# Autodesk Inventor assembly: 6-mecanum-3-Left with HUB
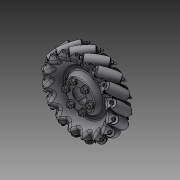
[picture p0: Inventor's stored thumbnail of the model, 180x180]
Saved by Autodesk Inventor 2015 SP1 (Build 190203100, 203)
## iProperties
Created: 2015-01
Part Number: 6-mecanum-3-Left with HUB
Document SubType Name: Assembly
Designer: TODD D MILLER
Mass: 713.537 g
Surface Area: 1552.75 cm^2
Volume: 208.67 cm^3
Density: 3.41946 g/cm^3
Author: TODD D MILLER
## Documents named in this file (4)
- C:\Users\TODD D MILLER\Documents\GrabCAD\ElkLogics FRC\CAD Library\Mecanum wheels\6-mecanum-3-Left with HUB.iam
- C:\Users\TODD D MILLER\Documents\GrabCAD\ElkLogics FRC\CAD Library\Mecanum wheels\6-mecanum-3-Left.iam
- C:\Users\TODD D MILLER\Documents\GrabCAD\ElkLogics FRC\CAD Library\Mecanum wheels\500EX-Key-Hub.ipt
- C:\Users\TODD D MILLER\Documents\GrabCAD\ElkLogics FRC\CAD Library\Mecanum wheels\6-mecanum-3-Left with HUB\Design Accelerator\Bolted Connection1.iam
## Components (3 placed, 3 different names)
1. 6-mecanum-3-Left:1 [sub-assembly] — Insert:1, Mate:1, Insert:2
2. 500EX-Key-Hub:1 — Insert:1, Insert:2, Mate:2, Mate:3
3. Bolted Connection:1 [sub-assembly] — Mate:2, Mate:3
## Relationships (5: Mate 3, Insert 2)
- Insert:1: 6-mecanum-3-Left:1 ↔ 500EX-Key-Hub:1
- Mate:1: 6-mecanum-3-Left:1
- Insert:2: 6-mecanum-3-Left:1 ↔ 500EX-Key-Hub:1
- Mate:2: 500EX-Key-Hub:1 ↔ Bolted Connection:1
- Mate:3: 500EX-Key-Hub:1 ↔ Bolted Connection:1
